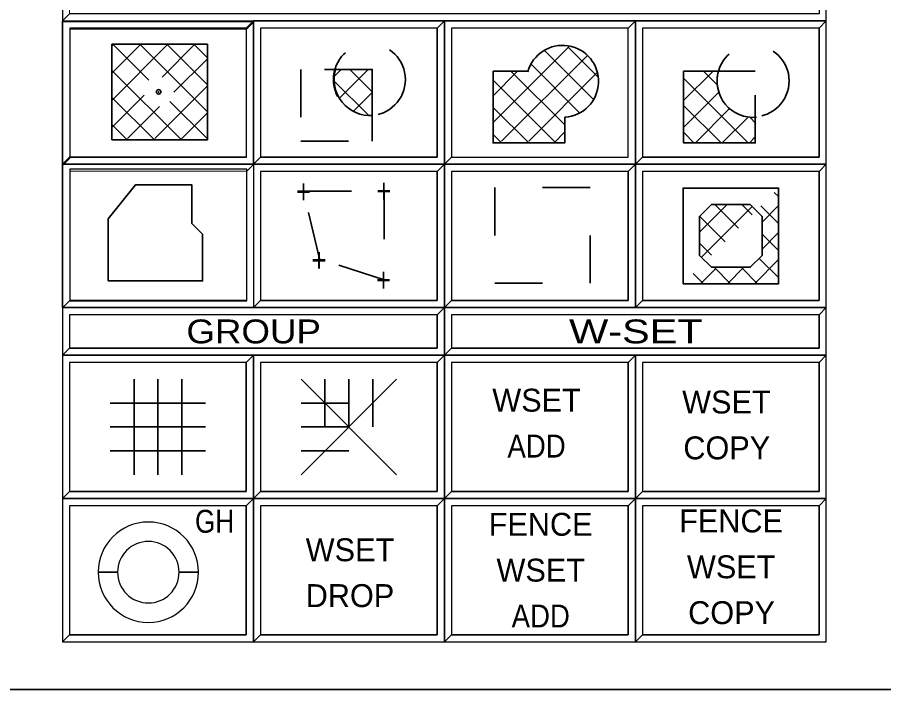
# Model space of a CAD drawing. Extents: x 95906.8 to 95923.6, y 90964.8 to 90972.8.
# Drawn here: x 95910.737 to 95912.552, y 90964.762 to 90966.169 of the extents above; entities that cross this region are included whole.
import ezdxf
from ezdxf.enums import TextEntityAlignment as Align

# ---------------------------------------------------------------- set-up
doc = ezdxf.new("R2010")
doc.units = 0
doc.header["$LTSCALE"] = 0.019
doc.header["$PDMODE"] = 32
doc.header["$PDSIZE"] = 0.0095
doc.linetypes.add('DOTTED', pattern=[1.5, 0.3, -1.2])
doc.linetypes.add('MEDIUM_DASHED', pattern=[4.5, 3, -1.5])
for name, color, linetype, lineweight in [('1', 7, 'Continuous', 25), ('11', 7, 'Continuous', 25), ('12', 7, 'Continuous', 25), ('16', 7, 'Continuous', 25), ('2', 7, 'Continuous', 13), ('3', 7, 'Continuous', 25), ('6', 7, 'Continuous', 35), ('7', 7, 'Continuous', 35)]:
    doc.layers.add(name, color=color, linetype=linetype, lineweight=lineweight)

msp = doc.modelspace()

# ---------------------------------------------------------------- linework, layer by layer
at = {"layer": '1'}
msp.add_line((95910.8316, 90966.1619), (95910.8316, 90965.858), dxfattribs=at)
for points in [[(95910.8318, 90966.1617), (95912.4318, 90966.1617), (95912.4318, 90966.2617), (95910.8318, 90966.2617)], [(95911.2318, 90965.8617), (95911.6318, 90965.8617), (95911.6318, 90966.1617), (95911.2318, 90966.1617)], [(95911.6318, 90965.8617), (95912.0318, 90965.8617), (95912.0318, 90966.1617), (95911.6318, 90966.1617)], [(95912.0318, 90965.8617), (95912.4318, 90965.8617), (95912.4318, 90966.1617), (95912.0318, 90966.1617)], [(95911.2318, 90965.5617), (95911.6318, 90965.5617), (95911.6318, 90965.8617), (95911.2318, 90965.8617)], [(95911.6318, 90965.5617), (95912.0318, 90965.5617), (95912.0318, 90965.8617), (95911.6318, 90965.8617)], [(95912.0318, 90965.5617), (95912.4318, 90965.5617), (95912.4318, 90965.8617), (95912.0318, 90965.8617)], [(95910.8318, 90965.4617), (95911.6318, 90965.4617), (95911.6318, 90965.5617), (95910.8318, 90965.5617)], [(95911.6318, 90965.4617), (95912.4318, 90965.4617), (95912.4318, 90965.5617), (95911.6318, 90965.5617)], [(95910.8318, 90965.1617), (95911.2318, 90965.1617), (95911.2318, 90965.4617), (95910.8318, 90965.4617)], [(95911.2318, 90965.1617), (95911.6318, 90965.1617), (95911.6318, 90965.4617), (95911.2318, 90965.4617)], [(95911.6318, 90965.1617), (95912.0318, 90965.1617), (95912.0318, 90965.4617), (95911.6318, 90965.4617)], [(95912.0318, 90965.1617), (95912.4318, 90965.1617), (95912.4318, 90965.4617), (95912.0318, 90965.4617)], [(95910.8318, 90964.8617), (95911.2318, 90964.8617), (95911.2318, 90965.1617), (95910.8318, 90965.1617)], [(95911.2318, 90964.8617), (95911.6318, 90964.8617), (95911.6318, 90965.1617), (95911.2318, 90965.1617)], [(95911.6318, 90964.8617), (95912.0318, 90964.8617), (95912.0318, 90965.1617), (95911.6318, 90965.1617)], [(95912.0318, 90964.8617), (95912.4318, 90964.8617), (95912.4318, 90965.1617), (95912.0318, 90965.1617)]]:
    msp.add_lwpolyline(points, close=True, dxfattribs=at)
msp.add_lwpolyline([(95911.2314, 90965.8618), (95910.8314, 90965.8618), (95910.8314, 90965.5618), (95911.2314, 90965.5618), (95911.2314, 90965.562)], dxfattribs=at)
at = {"layer": '11'}
for points in [[(95910.8477, 90965.8767), (95911.2177, 90965.8767), (95911.2177, 90966.1467), (95910.8477, 90966.1467)], [(95911.2468, 90965.8767), (95911.6168, 90965.8767), (95911.6168, 90966.1467), (95911.2468, 90966.1467)], [(95911.6468, 90965.8767), (95912.0168, 90965.8767), (95912.0168, 90966.1467), (95911.6468, 90966.1467)], [(95912.0468, 90965.8767), (95912.4168, 90965.8767), (95912.4168, 90966.1467), (95912.0468, 90966.1467)], [(95910.8477, 90965.5759), (95911.2179, 90965.5759), (95911.2179, 90965.8513), (95910.8477, 90965.8513)], [(95911.2468, 90965.5767), (95911.6168, 90965.5767), (95911.6168, 90965.8467), (95911.2468, 90965.8467)], [(95911.6468, 90965.5767), (95912.0168, 90965.5767), (95912.0168, 90965.8467), (95911.6468, 90965.8467)], [(95912.0468, 90965.5767), (95912.4168, 90965.5767), (95912.4168, 90965.8467), (95912.0468, 90965.8467)], [(95911.2468, 90965.1767), (95911.6168, 90965.1767), (95911.6168, 90965.4467), (95911.2468, 90965.4467)], [(95911.6468, 90965.1767), (95912.0168, 90965.1767), (95912.0168, 90965.4467), (95911.6468, 90965.4467)], [(95912.0468, 90965.1767), (95912.4168, 90965.1767), (95912.4168, 90965.4467), (95912.0468, 90965.4467)], [(95910.8468, 90964.8767), (95911.2168, 90964.8767), (95911.2168, 90965.1467), (95910.8468, 90965.1467)], [(95911.2468, 90964.8767), (95911.6168, 90964.8767), (95911.6168, 90965.1467), (95911.2468, 90965.1467)], [(95911.6468, 90964.8767), (95912.0168, 90964.8767), (95912.0168, 90965.1467), (95911.6468, 90965.1467)], [(95912.0468, 90964.8767), (95912.4168, 90964.8767), (95912.4168, 90965.1467), (95912.0468, 90965.1467)]]:
    msp.add_lwpolyline(points, close=True, dxfattribs=at)
at = {"layer": '12'}
msp.add_lwpolyline([(95910.8468, 90965.1767), (95911.2168, 90965.1767), (95911.2168, 90965.4467), (95910.8468, 90965.4467)], close=True, dxfattribs=at)
at = {"layer": '16'}
for points in [[(95910.8468, 90965.4767), (95911.6168, 90965.4767), (95911.6168, 90965.5467), (95910.8468, 90965.5467)], [(95911.6468, 90965.4767), (95912.4168, 90965.4767), (95912.4168, 90965.5467), (95911.6468, 90965.5467)]]:
    msp.add_lwpolyline(points, close=True, dxfattribs=at)
at = {"layer": '2'}
for points in [[(95910.8318, 90966.2617), (95910.8318, 90966.1617), (95910.8468, 90966.1767), (95910.8468, 90966.2467), (95912.4168, 90966.2467), (95912.4318, 90966.2617)], [(95910.8325, 90966.1596), (95910.8325, 90965.8596), (95910.8475, 90965.8746), (95910.8475, 90966.1446), (95911.2175, 90966.1446), (95911.2325, 90966.1596)], [(95911.2318, 90966.1617), (95911.2318, 90965.8617), (95911.2468, 90965.8767), (95911.2468, 90966.1467), (95911.6168, 90966.1467), (95911.6318, 90966.1617)], [(95911.6318, 90966.1617), (95911.6318, 90965.8617), (95911.6468, 90965.8767), (95911.6468, 90966.1467), (95912.0168, 90966.1467), (95912.0318, 90966.1617)], [(95912.0318, 90966.1617), (95912.0318, 90965.8617), (95912.0468, 90965.8767), (95912.0468, 90966.1467), (95912.4168, 90966.1467), (95912.4318, 90966.1617)], [(95910.8329, 90965.8621), (95910.8329, 90965.5621), (95910.8479, 90965.5771), (95910.8479, 90965.8471), (95911.2179, 90965.8471), (95911.2329, 90965.8621)], [(95911.2318, 90965.8617), (95911.2318, 90965.5617), (95911.2468, 90965.5767), (95911.2468, 90965.8467), (95911.6168, 90965.8467), (95911.6318, 90965.8617)], [(95911.6318, 90965.8617), (95911.6318, 90965.5617), (95911.6468, 90965.5767), (95911.6468, 90965.8467), (95912.0168, 90965.8467), (95912.0318, 90965.8617)], [(95912.0318, 90965.8617), (95912.0318, 90965.5617), (95912.0468, 90965.5767), (95912.0468, 90965.8467), (95912.4168, 90965.8467), (95912.4318, 90965.8617)], [(95910.8318, 90965.5617), (95910.8318, 90965.4617), (95910.8468, 90965.4767), (95910.8468, 90965.5467), (95911.6168, 90965.5467), (95911.6318, 90965.5617)], [(95911.6318, 90965.5617), (95911.6318, 90965.4617), (95911.6468, 90965.4767), (95911.6468, 90965.5467), (95912.4168, 90965.5467), (95912.4318, 90965.5617)], [(95910.8318, 90965.4617), (95910.8318, 90965.1617), (95910.8468, 90965.1767), (95910.8468, 90965.4467), (95911.2168, 90965.4467), (95911.2318, 90965.4617)], [(95911.2318, 90965.4617), (95911.2318, 90965.1617), (95911.2468, 90965.1767), (95911.2468, 90965.4467), (95911.6168, 90965.4467), (95911.6318, 90965.4617)], [(95911.6318, 90965.4617), (95911.6318, 90965.1617), (95911.6468, 90965.1767), (95911.6468, 90965.4467), (95912.0168, 90965.4467), (95912.0318, 90965.4617)], [(95912.0318, 90965.4617), (95912.0318, 90965.1617), (95912.0468, 90965.1767), (95912.0468, 90965.4467), (95912.4168, 90965.4467), (95912.4318, 90965.4617)], [(95910.8318, 90965.1617), (95910.8318, 90964.8617), (95910.8468, 90964.8767), (95910.8468, 90965.1467), (95911.2168, 90965.1467), (95911.2318, 90965.1617)], [(95911.2318, 90965.1617), (95911.2318, 90964.8617), (95911.2468, 90964.8767), (95911.2468, 90965.1467), (95911.6168, 90965.1467), (95911.6318, 90965.1617)], [(95911.6318, 90965.1617), (95911.6318, 90964.8617), (95911.6468, 90964.8767), (95911.6468, 90965.1467), (95912.0168, 90965.1467), (95912.0318, 90965.1617)], [(95912.0318, 90965.1617), (95912.0318, 90964.8617), (95912.0468, 90964.8767), (95912.0468, 90965.1467), (95912.4168, 90965.1467), (95912.4318, 90965.1617)]]:
    msp.add_lwpolyline(points, close=True, dxfattribs=at)
at = {"layer": '3'}
for points in [[(95910.8318, 90966.1617), (95912.4318, 90966.1617), (95912.4318, 90966.2617), (95912.4168, 90966.2467), (95912.4168, 90966.1767), (95910.8468, 90966.1767)], [(95910.8318, 90965.8617), (95911.2318, 90965.8617), (95911.2318, 90966.1617), (95911.2168, 90966.1467), (95911.2168, 90965.8767), (95910.8468, 90965.8767)], [(95911.2318, 90965.8617), (95911.6318, 90965.8617), (95911.6318, 90966.1617), (95911.6168, 90966.1467), (95911.6168, 90965.8767), (95911.2468, 90965.8767)], [(95912.0318, 90965.8617), (95912.4318, 90965.8617), (95912.4318, 90966.1617), (95912.4168, 90966.1467), (95912.4168, 90965.8767), (95912.0468, 90965.8767)], [(95910.8325, 90965.5618), (95911.2325, 90965.5618), (95911.2325, 90965.8618), (95911.2175, 90965.8468), (95911.2175, 90965.5768), (95910.8475, 90965.5768)], [(95911.2318, 90965.5617), (95911.6318, 90965.5617), (95911.6318, 90965.8617), (95911.6168, 90965.8467), (95911.6168, 90965.5767), (95911.2468, 90965.5767)], [(95911.6318, 90965.5617), (95912.0318, 90965.5617), (95912.0318, 90965.8617), (95912.0168, 90965.8467), (95912.0168, 90965.5767), (95911.6468, 90965.5767)], [(95912.0318, 90965.5617), (95912.4318, 90965.5617), (95912.4318, 90965.8617), (95912.4168, 90965.8467), (95912.4168, 90965.5767), (95912.0468, 90965.5767)], [(95910.8318, 90965.4617), (95911.6318, 90965.4617), (95911.6318, 90965.5617), (95911.6168, 90965.5467), (95911.6168, 90965.4767), (95910.8468, 90965.4767)], [(95911.6318, 90965.4617), (95912.4318, 90965.4617), (95912.4318, 90965.5617), (95912.4168, 90965.5467), (95912.4168, 90965.4767), (95911.6468, 90965.4767)], [(95910.8318, 90965.1617), (95911.2318, 90965.1617), (95911.2318, 90965.4617), (95911.2168, 90965.4467), (95911.2168, 90965.1767), (95910.8468, 90965.1767)], [(95911.2318, 90965.1617), (95911.6318, 90965.1617), (95911.6318, 90965.4617), (95911.6168, 90965.4467), (95911.6168, 90965.1767), (95911.2468, 90965.1767)], [(95911.6318, 90965.1617), (95912.0318, 90965.1617), (95912.0318, 90965.4617), (95912.0168, 90965.4467), (95912.0168, 90965.1767), (95911.6468, 90965.1767)], [(95912.0318, 90965.1617), (95912.4318, 90965.1617), (95912.4318, 90965.4617), (95912.4168, 90965.4467), (95912.4168, 90965.1767), (95912.0468, 90965.1767)], [(95910.8318, 90964.8617), (95911.2318, 90964.8617), (95911.2318, 90965.1617), (95911.2168, 90965.1467), (95911.2168, 90964.8767), (95910.8468, 90964.8767)], [(95911.2318, 90964.8617), (95911.6318, 90964.8617), (95911.6318, 90965.1617), (95911.6168, 90965.1467), (95911.6168, 90964.8767), (95911.2468, 90964.8767)], [(95911.6318, 90964.8617), (95912.0318, 90964.8617), (95912.0318, 90965.1617), (95912.0168, 90965.1467), (95912.0168, 90964.8767), (95911.6468, 90964.8767)], [(95912.0318, 90964.8617), (95912.4318, 90964.8617), (95912.4318, 90965.1617), (95912.4168, 90965.1467), (95912.4168, 90964.8767), (95912.0468, 90964.8767)]]:
    msp.add_lwpolyline(points, close=True, dxfattribs=at)
at = {"layer": '6', "lineweight": 13}
for p, q in [((95910.8318, 90965.8617), (95910.8318, 90966.1617)), ((95910.9354, 90965.9955), (95911.0527, 90966.1128)), ((95910.9354, 90966.0521), (95910.9961, 90966.1128)), ((95910.9354, 90966.1087), (95910.9395, 90966.1128)), ((95910.9374, 90966.1128), (95911.0128, 90966.0375)), ((95910.994, 90966.1128), (95911.1355, 90965.9713)), ((95911.0405, 90966.0441), (95911.1092, 90966.1128)), ((95911.0506, 90966.1128), (95911.0972, 90966.0662)), ((95911.1071, 90966.1128), (95911.1354, 90966.0845)), ((95911.7341, 90965.9489), (95911.8925, 90966.1073)), ((95911.8407, 90966.1005), (95911.8805, 90966.0607)), ((95911.8904, 90966.1073), (95911.9539, 90966.0438)), ((95911.0652, 90966.0123), (95911.1354, 90966.0824)), ((95911.7517, 90965.9099), (95911.9306, 90966.0887)), ((95911.0977, 90966.0657), (95911.1354, 90966.028)), ((95911.3994, 90966.0439), (95911.4157, 90966.0601)), ((95911.4122, 90966), (95911.4723, 90966.0602)), ((95911.4343, 90966.0592), (95911.4812, 90966.0123)), ((95911.8144, 90966.0703), (95911.9152, 90965.9695)), ((95911.881, 90966.0602), (95911.9442, 90965.997)), ((95910.9354, 90966.0583), (95911.0797, 90965.914)), ((95911.7338, 90966.0051), (95911.7845, 90966.0558)), ((95911.772, 90966.0562), (95911.8847, 90965.9437)), ((95911.8084, 90965.91), (95911.9529, 90966.0545)), ((95912.1334, 90966.0411), (95912.2682, 90965.9063)), ((95912.134, 90965.9963), (95912.1932, 90966.0555)), ((95912.1751, 90966.056), (95912.2038, 90966.0273)), ((95911.0251, 90965.9155), (95911.1354, 90966.0258)), ((95911.4011, 90966.0359), (95911.4727, 90965.9644)), ((95911.7354, 90966.0361), (95911.863, 90965.9085)), ((95910.9354, 90965.939), (95911.003, 90966.0066)), ((95911.4404, 90965.9717), (95911.481, 90966.0123)), ((95912.133, 90965.9387), (95912.2067, 90966.0124)), ((95910.9354, 90966.0017), (95911.0252, 90965.9119)), ((95911.0571, 90965.9931), (95911.1349, 90965.9153)), ((95910.9684, 90965.9154), (95911.0353, 90965.9823)), ((95911.0789, 90965.9128), (95911.1354, 90965.9693)), ((95911.7355, 90965.9794), (95911.8085, 90965.9064)), ((95912.1329, 90965.985), (95912.2116, 90965.9063)), ((95912.1577, 90965.9069), (95912.2284, 90965.9777)), ((95912.2144, 90965.907), (95912.2666, 90965.9591)), ((95912.2713, 90965.96), (95912.284, 90965.9473)), ((95910.9354, 90965.9451), (95910.9677, 90965.9128)), ((95911.7336, 90965.9247), (95911.751, 90965.9073)), ((95911.8622, 90965.9073), (95911.8842, 90965.9293)), ((95912.1333, 90965.928), (95912.1552, 90965.9061)), ((95912.27, 90965.9061), (95912.2834, 90965.9195)), ((95912.3229, 90965.8028), (95912.3318, 90965.794)), ((95912.1661, 90965.7195), (95912.224, 90965.7774)), ((95912.1701, 90965.667), (95912.2765, 90965.7734)), ((95912.1984, 90965.7774), (95912.248, 90965.7279)), ((95912.255, 90965.7774), (95912.2762, 90965.7561)), ((95912.2947, 90965.7746), (95912.3318, 90965.7374)), ((95912.3318, 90965.7752), (95912.2979, 90965.7413)), ((95912.1665, 90965.7528), (95912.2197, 90965.6996)), ((95912.3318, 90965.6808), (95912.2968, 90965.7158)), ((95912.3318, 90965.7187), (95912.2978, 90965.6847)), ((95912.1661, 90965.6966), (95912.1914, 90965.6713)), ((95912.2814, 90965.6117), (95912.3318, 90965.6621)), ((95912.3318, 90965.6243), (95912.2907, 90965.6653)), ((95912.1683, 90965.6117), (95912.1989, 90965.6423)), ((95912.2312, 90965.6117), (95912.1974, 90965.6455)), ((95912.2248, 90965.6117), (95912.2584, 90965.6453)), ((95912.2878, 90965.6117), (95912.2548, 90965.6447)), ((95912.1532, 90965.6331), (95912.1747, 90965.6117))]:
    msp.add_line(p, q, dxfattribs=at)
at = {"layer": '6'}
for p, q in [((95911.8074, 90966.0563), (95911.7343, 90966.0563)), ((95910.8318, 90965.5617), (95911.9238, 90965.5617)), ((95910.9818, 90965.4117), (95910.9818, 90965.2117)), ((95911.0318, 90965.4117), (95911.0318, 90965.2117)), ((95911.0818, 90965.4117), (95911.0818, 90965.2117)), ((95911.3318, 90965.2117), (95911.5318, 90965.4117)), ((95911.3318, 90965.4117), (95911.5318, 90965.2117)), ((95910.9318, 90965.3617), (95911.1318, 90965.3617)), ((95910.9318, 90965.3117), (95911.1318, 90965.3117)), ((95910.9318, 90965.2617), (95911.1318, 90965.2617))]:
    msp.add_line(p, q, dxfattribs=at)
at = {"layer": '6', "linetype": 'MEDIUM_DASHED'}
for p, q in [((95911.3818, 90965.4117), (95911.3818, 90965.2117)), ((95911.4318, 90965.4117), (95911.4318, 90965.2117)), ((95911.4818, 90965.4117), (95911.4818, 90965.2117)), ((95911.3318, 90965.3617), (95911.5318, 90965.3617)), ((95911.3318, 90965.3117), (95911.5318, 90965.3117)), ((95911.3318, 90965.2617), (95911.5318, 90965.2617))]:
    msp.add_line(p, q, dxfattribs=at)
at = {"layer": '6', "lineweight": 25}
for p, q in [((95910.9068, 90965.0076), (95910.9475, 90965.0076)), ((95910.9475, 90965.0076), (95910.9068, 90965.0076)), ((95911.0763, 90965.0076), (95911.117, 90965.0076)), ((95911.117, 90965.0076), (95911.0763, 90965.0076))]:
    msp.add_line(p, q, dxfattribs=at)
at = {"layer": '6'}
for points in [[(95910.9354, 90965.9128), (95911.1354, 90965.9128), (95911.1354, 90966.1128), (95910.9354, 90966.1128)], [(95910.9279, 90965.6175), (95910.9279, 90965.7476), (95910.9848, 90965.8186), (95911.0827, 90965.8186), (95911.1031, 90965.8186), (95911.1027, 90965.738), (95911.1254, 90965.7153), (95911.1254, 90965.6175)], [(95912.1318, 90965.6117), (95912.3318, 90965.6117), (95912.3318, 90965.8117), (95912.1318, 90965.8117)], [(95912.1911, 90965.646), (95912.2725, 90965.646), (95912.2975, 90965.671), (95912.2975, 90965.7524), (95912.2725, 90965.7774), (95912.1911, 90965.7774), (95912.1661, 90965.7524), (95912.1661, 90965.671)]]:
    msp.add_lwpolyline(points, close=True, dxfattribs=at)
at = {"layer": '6', "linetype": 'DOTTED'}
for points in [[(95911.3309, 90965.9101), (95911.4809, 90965.9101), (95911.4809, 90966.0601), (95911.3309, 90966.0601)], [(95912.133, 90965.9063), (95912.283, 90965.9063), (95912.283, 90966.0563), (95912.133, 90966.0563)], [(95911.7374, 90965.6128), (95911.9374, 90965.6128), (95911.9374, 90965.8128), (95911.7374, 90965.8128)]]:
    msp.add_lwpolyline(points, close=True, dxfattribs=at)
at = {"layer": '6'}
for points in [[(95911.4809, 90965.9594), (95911.4809, 90966.0601), (95911.4057, 90966.0601)], [(95911.7339, 90966.0566), (95911.7339, 90965.9063), (95911.8839, 90965.9063), (95911.8839, 90965.9601)], [(95912.2079, 90966.0563), (95912.133, 90966.0563), (95912.133, 90965.9063), (95912.283, 90965.9063), (95912.283, 90965.9622)]]:
    msp.add_lwpolyline(points, dxfattribs=at)
at = {"layer": '6', "linetype": 'MEDIUM_DASHED'}
msp.add_lwpolyline([(95911.337, 90965.8051), (95911.5058, 90965.8051), (95911.5058, 90965.6197), (95911.3704, 90965.6634)], close=True, dxfattribs=at)
at = {"layer": '6', "linetype": 'DOTTED'}
for centre in [(95911.4748, 90966.0391), (95912.2784, 90966.0362)]:
    msp.add_circle(centre, 0.0754, dxfattribs=at)
at = {"layer": '6'}
for centre, start, end in [((95911.8793, 90966.0353), 273.8644, 164.6109), ((95911.4763, 90966.0391), 163.6588, 274.1636), ((95912.2784, 90966.0353), 162.9658, 275.5202)]:
    msp.add_arc(centre, 0.0754, start, end, dxfattribs=at)
at = {"layer": '6', "lineweight": 25}
for centre, radius, start, end in [((95911.012, 90965.0075), 0.1052, 90.0315, 179.9685), ((95911.0118, 90965.0075), 0.1052, 0.0315, 89.9685), ((95911.0117, 90965.0078), 0.0642, 89.8108, 180.1892), ((95911.0121, 90965.0078), 0.0642, 359.8108, 90.1892), ((95911.012, 90965.0077), 0.1052, 180.0315, 269.9685), ((95911.0117, 90965.0074), 0.0642, 179.8108, 270.1892), ((95911.0118, 90965.0077), 0.1052, 270.0315, 359.9685), ((95911.0121, 90965.0074), 0.0642, 269.8108, 0.1892)]:
    msp.add_arc(centre, radius, start, end, dxfattribs=at)
at = {"layer": '6'}
msp.add_point((95911.0334, 90966.0133), dxfattribs=at)
at = {"layer": '7'}
msp.add_lwpolyline([(95906.8323, 90972.7617), (95918.8323, 90972.7617), (95918.8323, 90964.7617), (95906.8323, 90964.7617)], close=True, dxfattribs=at)

# ---------------------------------------------------------------- texts
at = {"layer": '6', "width": 0.8}
for p in [(95911.4893, 90965.781), (95911.3213, 90965.7801), (95911.3537, 90965.6364), (95911.4888, 90965.5949)]:
    msp.add_text('+', height=0.05, dxfattribs=at).set_placement(p)
at = {"layer": '6'}
for s, p in [('WSET', (95911.8249, 90965.3437)), ('WSET', (95912.2225, 90965.3399)), ('COPY', (95912.2233, 90965.2439)), ('FENCE', (95912.2323, 90965.0909)), ('FENCE', (95911.8334, 90965.0839)), ('WSET', (95911.4341, 90965.0306)), ('WSET', (95912.2326, 90964.9949)), ('WSET', (95911.8337, 90964.9879)), ('DROP', (95911.4341, 90964.9346)), ('COPY', (95912.2334, 90964.8989))]:
    msp.add_text(s, height=0.048, dxfattribs=at).set_placement(p, align=Align.CENTER)
for s, width, p in [('ADD', 0.9, (95911.8249, 90965.2477)), ('GH', 0.85, (95911.1505, 90965.0902)), ('ADD', 0.9, (95911.8337, 90964.8919))]:
    msp.add_text(s, height=0.048, dxfattribs=dict(at, width=width)).set_placement(p, align=Align.CENTER)
at = {"layer": '7'}
for s, width, p in [('GROUP', 1.15, (95911.2324, 90965.4867)), ('W-SET', 1.3, (95912.033, 90965.4867))]:
    msp.add_text(s, height=0.04999, dxfattribs=dict(at, width=width)).set_placement(p, align=Align.CENTER)

doc.saveas('drawing.dxf')
